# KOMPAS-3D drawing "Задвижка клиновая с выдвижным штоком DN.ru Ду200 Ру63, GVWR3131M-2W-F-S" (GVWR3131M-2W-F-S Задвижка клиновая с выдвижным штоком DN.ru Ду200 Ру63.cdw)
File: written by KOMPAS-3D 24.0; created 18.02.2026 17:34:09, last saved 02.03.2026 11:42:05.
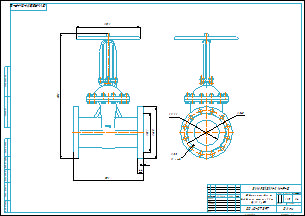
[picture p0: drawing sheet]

Document properties: art: D040-07397; Автор: R2D2; Форматы листов документа: A2; Полное имя файла: GVWR3131M-2W-F-S Задвижка клиновая с выдвижным штоком DN.ru Ду200 Ру63.m3d; Масса: 209; Наименование: Задвижка клиновая с выдвижным штоком DN.ru Ду200 Ру63; Количество листов документа: 1; Примечание: D040-07397

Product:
- Part/product: Задвижка клиновая с выдвижным штоком DN.ru Ду200 Ру63  | designation GVWR3131M-2W-F-S
    Масса: 209
    Раздел спецификации: Прочие изделия
    Примечание: D040-07397
    additional columns: D040-07397

Referenced files in E:\Работа\Зайцев\Для компаса\: чертеж DN.ru А3.cdt
Referenced files in E:\Работа\Зайцев\GVWR3131M-2W-F-S Задвижка клиновая с выдвижным штоком DN.ru Ду50-200 Ру63\DN200\: GVWR3131M-2W-F-S Задвижка клиновая с выдвижным штоком DN.ru Ду200 Ру63.m3d
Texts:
  чертеж DN.ru А3.cdt
  Задвижка клиновая с
  выдвижным штоком DN.ru
  Ду200 Ру63
  GVWR3131M-2W-F-S
  Задвижка клиновая с выдвижным штоком DN.ru Ду200 Ру63
  GVWR3131M-2W-F-S Задвижка клиновая с выдвижным штоком DN.ru Ду200 Ру63
Dimensions and other numbers on the sheet: 1:4; 0; 1; 2; 209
